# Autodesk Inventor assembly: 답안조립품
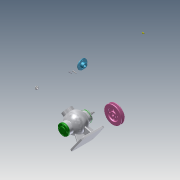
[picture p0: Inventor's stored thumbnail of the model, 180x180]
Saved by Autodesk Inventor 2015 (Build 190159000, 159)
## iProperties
Created: 2025-08
Part Number: 답안조립품
Document SubType Name: Assembly
Designer: user
Author: user
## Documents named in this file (15)
- C:\Users\user\Desktop\750808V1001\답안조립품.iam
- C:\Users\user\Desktop\750808V1001\가져온 구성요소\편심축\편심축.ipt
- C:\Users\user\Desktop\750808V1001\가져온 구성요소\V-벨트풀리\V-벨트풀리.ipt
- C:\Users\user\Desktop\750808V1001\가져온 구성요소\너트 M8\너트 M8.ipt
- C:\Users\user\Desktop\750808V1001\가져온 구성요소\뒤커버\뒤커버.ipt
- C:\Users\user\Desktop\750808V1001\가져온 구성요소\베어링- 6202\베어링- 6202.ipt
- C:\Users\user\Desktop\750808V1001\가져온 구성요소\볼트 M4 x 12\볼트 M4 x 12.ipt
- C:\Users\user\Desktop\750808V1001\가져온 구성요소\볼트 M4 x 16\볼트 M4 x 16.ipt
- C:\Users\user\Desktop\750808V1001\가져온 구성요소\상부커버\상부커버.ipt
- C:\Users\user\Desktop\750808V1001\가져온 구성요소\슬라이드\슬라이드.ipt
- C:\Users\user\Desktop\750808V1001\가져온 구성요소\앞커버\앞커버.ipt
- C:\Users\user\Desktop\750808V1001\가져온 구성요소\오일실 15 30 7\오일실 15 30 7.ipt
- C:\Users\user\Desktop\750808V1001\가져온 구성요소\칼라\칼라.ipt
- C:\Users\user\Desktop\750808V1001\가져온 구성요소\키 4 x 4 x 12\키 4 x 4 x 12.ipt
- C:\Users\user\Desktop\750808V1001\본체.ipt
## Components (1 placed, 1 different names)
1. V-벨트풀리:1
## Named parameters: d1_d0 = 0
